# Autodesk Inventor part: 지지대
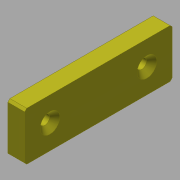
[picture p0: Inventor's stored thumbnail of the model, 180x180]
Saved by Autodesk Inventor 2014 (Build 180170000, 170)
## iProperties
Created: 2017-04
Part Number: 지지대
Material: 강철
Document SubType Name: Modeling
Designer: mduedu
Density: 7.85 g/cm^3
Appearance: 밝은 황색
Mass: 98.0769 g
Surface Area: 48.2288 cm^2
Volume: 12.4939 cm^3
Author: mduedu
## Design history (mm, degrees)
sketch "스케치1"
  geometry: L1 (23, -35)-(23, 35); L2 (0, -35)-(0, 35); L3 (0, 35)-(23, 35); L4 (0, -35)-(23, -35); 2 further points
  constraints: 8 end point, 2 parallel, 1 coincident, 1 midpoint, 1 perpendicular, 1 vertical
  dimensions: "d1" = 23 distance between parallel lines of L2 L1; "d15" = 70 distance of L1.start L1.end
extrude "돌출1" new body sketch "스케치1" distance "d2" = 8; taper "d3" = 0 deg
chamfer "모따기2" distance "d16" = 1; stored, may be unused: second distance "d17" = 2, angle "d18" = 45 deg
sketch "스케치2"
  geometry: L1 (1, -35)-(22, -35) reference; L2 (23, -34)-(23, 34) reference; L3 (22, 35)-(1, 35) reference; L4 (0, 34)-(0, -34) reference; L5 (11.5, 35)-(11.5, -35); L6 (23, 0)-(0, 0); L7 (1, -35)-(0, -34) reference; L8 (23, -34)-(22, -35) reference; L9 (22, 35)-(23, 34) reference; L10 (0, 34)-(1, 35) reference; 2 further points
  constraints: 4 end point, 4 midpoint, 1 point on line, 1 symmetric about line
  dimensions: "d7" = 12 distance from line of point (11.5, 23) L3
  node "투영된 루프1"
sketch "스케치3"
  geometry: 4 further points
  constraints: 2 coincident
hole "구멍1" sketch "스케치3" at (11.5, 23), (11.5, -23) diameter "d8" = 4.5; stored, may be unused: countersink angle "d12" = 90 deg, drill point angle "d14" = 0 deg; dims "d9" = 6, "d10" = 9.4, "d11" = 2, "d13" = 8
node "솔리드2"
node "솔리드1"
